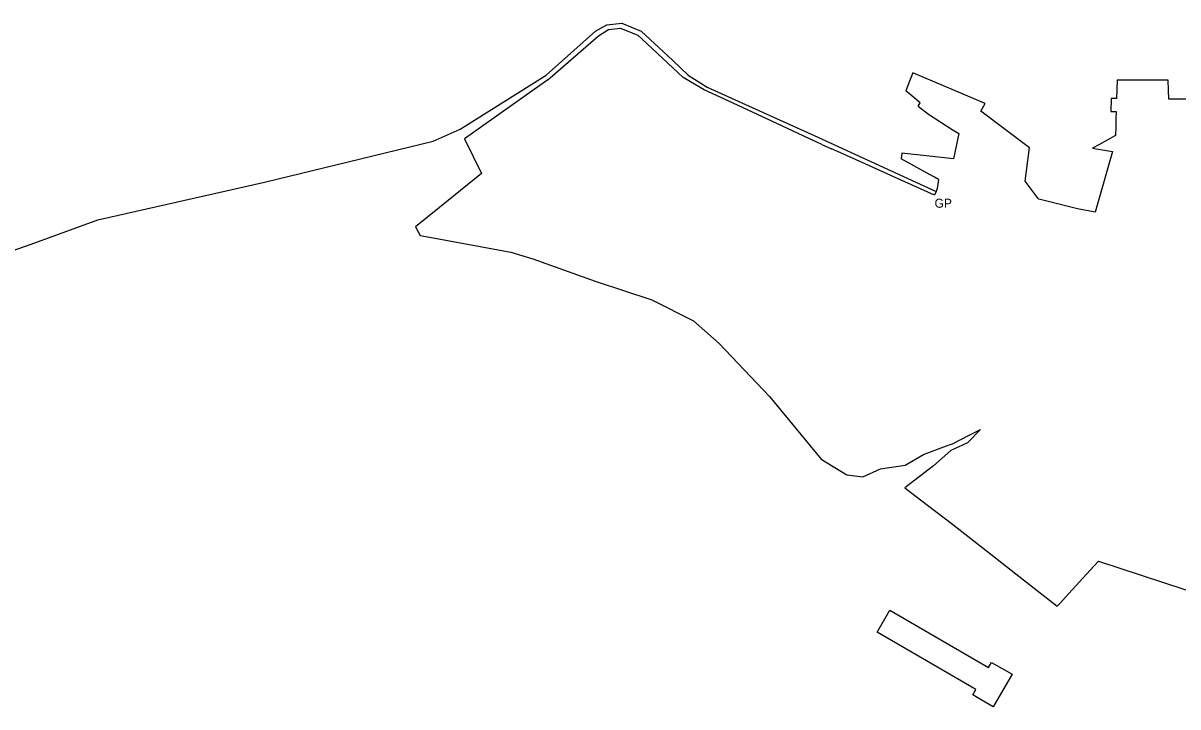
# Model space of a CAD drawing. Extents: x -587103 to -585114, y -1103460 to -1100918.
# Drawn here: x -586156 to -585642, y -1102327 to -1102023 of the extents above; entities that cross this region are included whole.
import ezdxf

# ---------------------------------------------------------------- set-up
doc = ezdxf.new("R2010")
doc.units = 0
for name, color, linetype in [('OVNI_POP', 7, 'Continuous'), ('OVNI_PRE', 7, 'Continuous'), ('OVNI_SET', 7, 'Continuous'), ('VODA', 7, 'Continuous')]:
    doc.layers.add(name, color=color, linetype=linetype)

msp = doc.modelspace()

# ---------------------------------------------------------------- linework, layer by layer
at = {"layer": 'OVNI_PRE'}
msp.add_lwpolyline([(-585770.55, -1102283.77), (-585726.72, -1102309.25), (-585725.35, -1102307), (-585720.67, -1102309.73), (-585716.27, -1102312.29), (-585724.63, -1102326.79), (-585731.8, -1102322.54), (-585733.7, -1102321.44), (-585732.34, -1102319.03), (-585776.23, -1102293.58)], close=True, dxfattribs=at)
at = {"layer": 'OVNI_SET'}
for points in [[(-585922.8, -1102047.94), (-585900.26, -1102028.36), (-585895.81, -1102025.49), (-585890.37, -1102025.02), (-585882.74, -1102028.08)], [(-585800.93, -1102076.67), (-585803.44, -1102075.5), (-585806.59, -1102074.03), (-585820.82, -1102067.4), (-585840.33, -1102058.3), (-585847.73, -1102054.85), (-585853.16, -1102052.32), (-585861.78, -1102047.39), (-585862.55, -1102046.95), (-585880.8, -1102029.9), (-585882.74, -1102028.08)], [(-585709.2, -1102083.85), (-585708.45, -1102078.2), (-585730.13, -1102061.91), (-585728.24, -1102058.42), (-585760.34, -1102044.81), (-585761.85, -1102048.59), (-585763.57, -1102052.88)], [(-585922.8, -1102047.94), (-585959.78, -1102074.17), (-585952.23, -1102089.66), (-585970.94, -1102104.73), (-585981.56, -1102113.29), (-585979.59, -1102117.18), (-585972.13, -1102118.52), (-585939.27, -1102124.55), (-585929.49, -1102127.51)], [(-585638.17, -1102056.49), (-585646.58, -1102056.46), (-585646.72, -1102052.57), (-585646.88, -1102048.15), (-585659.75, -1102048.09), (-585665.81, -1102048.06), (-585669.47, -1102048.04), (-585669.74, -1102056.2), (-585672.17, -1102056.19), (-585672.36, -1102062.05), (-585669.93, -1102062.06), (-585670.04, -1102065.33), (-585670.15, -1102068.85), (-585670.27, -1102072.64), (-585677.65, -1102076.77), (-585680.5, -1102078.37), (-585671.52, -1102079.83), (-585679.22, -1102106.8), (-585687.13, -1102105.28), (-585704.37, -1102101.01), (-585705.07, -1102100.08), (-585710.42, -1102093.05), (-585709.2, -1102083.85)], [(-585757.98, -1102059.68), (-585757.19, -1102058.09), (-585763.57, -1102052.88)], [(-585757.98, -1102059.68), (-585753.43, -1102063.23), (-585742.93, -1102070.07), (-585739.87, -1102071.78), (-585742.36, -1102083.06)], [(-585800.93, -1102076.67), (-585796.5, -1102078.62)], [(-585750.81, -1102099.26), (-585766.97, -1102091.96), (-585781.25, -1102085.51), (-585794.22, -1102079.65), (-585796.5, -1102078.62)], [(-585742.36, -1102083.06), (-585765.31, -1102080.58), (-585765.54, -1102083.12)], [(-585748.97, -1102092.19), (-585750.8, -1102091.19), (-585754.36, -1102089.24), (-585765.54, -1102083.12)], [(-585749.58, -1102096.21), (-585750.08, -1102097.65), (-585750.81, -1102099.26)], [(-585748.97, -1102092.19), (-585749.58, -1102096.21)], [(-585929.49, -1102127.51), (-585901.71, -1102137.42), (-585876.45, -1102145.83), (-585857.89, -1102155.16), (-585846.6, -1102165.18), (-585824.09, -1102188.75), (-585801.1, -1102216.57), (-585789.77, -1102223.58), (-585786.22, -1102224.02)], [(-585786.22, -1102224.02), (-585782.69, -1102224.45), (-585774.8, -1102220.89), (-585763.82, -1102219.24), (-585755.6, -1102214.61), (-585745.41, -1102210.72), (-585744.66, -1102210.44), (-585742.68, -1102209.79), (-585735.37, -1102205.97), (-585730.36, -1102203.36), (-585736.13, -1102209.35), (-585741.83, -1102212.05), (-585743.49, -1102212.71), (-585751.27, -1102219.6)], [(-585751.27, -1102219.6), (-585763.99, -1102229.38), (-585753.91, -1102237.01), (-585742.71, -1102245.48), (-585725.72, -1102258.89), (-585714.57, -1102267.6), (-585701.65, -1102277.69), (-585696.16, -1102281.98)], [(-585691.04, -1102276.4), (-585681.53, -1102266.04), (-585677.84, -1102262.03), (-585610.46, -1102284.12)], [(-585691.04, -1102276.4), (-585695.21, -1102280.94), (-585696.16, -1102281.98)]]:
    msp.add_lwpolyline(points, dxfattribs=at)
at = {"layer": 'VODA'}
msp.add_lwpolyline([(-586206.17, -1102139.83), (-586151.02, -1102120.36), (-586122.99, -1102110.12), (-586048.86, -1102093.49), (-585973.71, -1102075.24), (-585961.82, -1102069.86), (-585923.54, -1102045.83), (-585901.6, -1102026.26), (-585896.52, -1102023.52), (-585889.82, -1102022.71), (-585881.29, -1102026.36), (-585867.27, -1102039.24), (-585860.37, -1102045.83), (-585851.84, -1102051.2), (-585802.58, -1102073.41), (-585750.08, -1102097.65)], dxfattribs=at)

# ---------------------------------------------------------------- texts
at = {"layer": 'OVNI_POP'}
msp.add_text('GP  ', height=4, dxfattribs=at).set_placement((-585750.72, -1102104.81))

doc.saveas('drawing.dxf')
